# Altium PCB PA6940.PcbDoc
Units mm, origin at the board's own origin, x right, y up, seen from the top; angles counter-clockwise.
Board outline 34.99 x 16 mm, 2 copper layers (Top Layer, Bottom Layer), stack 1.57 mm thick; 7 components, 10 nets, 38 pads, 75 vias.
Unrouted connection lines stored in the file: 10.
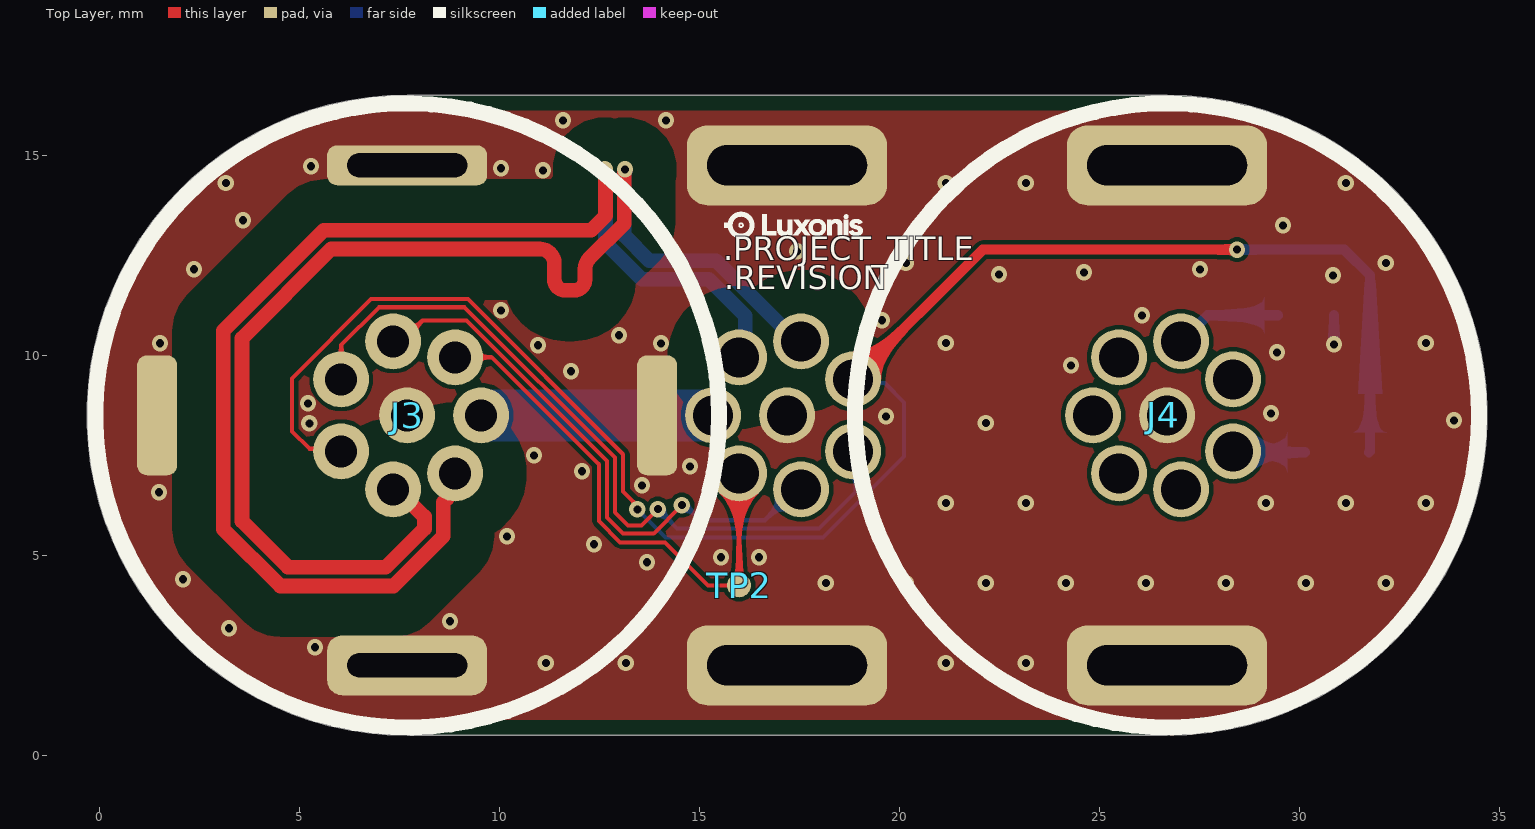
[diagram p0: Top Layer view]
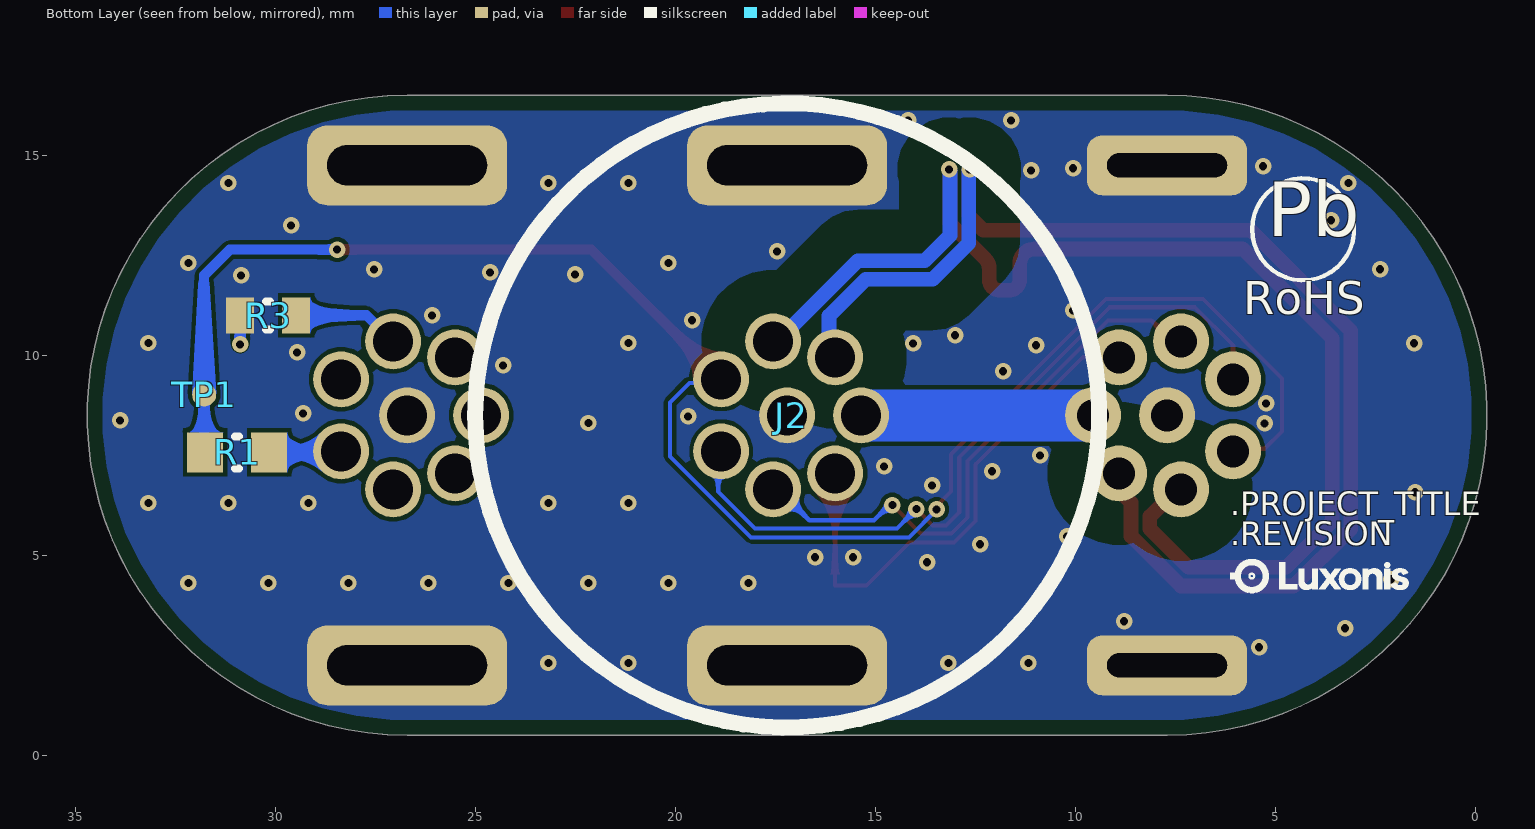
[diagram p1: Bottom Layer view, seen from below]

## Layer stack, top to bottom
Top Solder: solder mask 0.0254, SM-001, Dk 4
Top Layer: signal copper 0.035
Dielectric 1: core 1.5, Core-043, Dk 4.3
Bottom Layer: signal copper 0.035
Bottom Solder: solder mask 0.0254, SM-001, Dk 4

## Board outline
7.703,0.5 cw(c7.703,8.5) 7.703,16.5 26.7,16.5 cw(c26.7,8.5) 26.7,0.5

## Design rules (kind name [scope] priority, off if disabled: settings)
AssemblyTestPointUsage [All] p1: valid=2
AssemblyTestpoint [(IsPad And (OnTopLayer Or OnBottomLayer)) Or (IsVia) Or (IsPad And OnMultiLayer)] p1: testpointundercomponent=FALSE minsize=0.381 maxsize=2.54 preferedsize=1.524 minholesize=0 maxholesize=2.54 preferedholesize=0.813 testpointgrid=0.025 usegrid=FALSE gridtolerance=0 allowsidebottom=TRUE
BoardOutlineClearance [not InPolygonClass('ToEdge')] p1: gap=0.381 ignorepadtopadclearanceinfootprint=FALSE
Clearance DIFF_PAIR_GND [InPolygon vs InAnyDifferentialPair] p1: gap=1.08 ignorepadtopadclearanceinfootprint=FALSE
Clearance [All] p2: gap=0.1 ignorepadtopadclearanceinfootprint=FALSE
ComponentClearance [HasFootprint('FIDUCIAL_ROUND_1MM') or HasFootprint('TP100_200_NS') vs HasFootprint('FIDUCIAL_ROUND_1MM') or HasFootprint('TP100_200_NS')] p1: gap=-0.003 collisioncheckmode=3 verticalgap=2540 showdistances=FALSE
DiffPairsRouting 90ohm [InDifferentialPair('USB_D')] p1: maxlimit=0.1 minlimit=0.1 mostfreqgap=0.1 toplayer_minwidth=0.366 toplayer_maxwidth=0.366 toplayer_prefwidth=0.366 bottomlayer_minwidth=0.366 bottomlayer_maxwidth=0.366 bottomlayer_prefwidth=0.366 impedanceprofiledriven=TRUE impedanceprofileid={4F08DFFA-C90D-4D92-B63A-58C89057396F} impedanceprofilevalue=90.000000 maxuncoupledlength=12.7
DiffPairsRouting 100ohm [InDifferentialPairClass('100ohm')] p2: maxlimit=0.11 minlimit=0.11 mostfreqgap=0.11 toplayer_minwidth=0.173 toplayer_maxwidth=0.173 toplayer_prefwidth=0.173 bottomlayer_minwidth=0.173 bottomlayer_maxwidth=0.173 bottomlayer_prefwidth=0.173 maxuncoupledlength=12.7
FabricationTestPointUsage [All] p1: valid=2 allowmultiple=TRUE
FabricationTestpoint [(IsPad And (OnTopLayer Or OnBottomLayer)) Or (IsVia) Or (IsPad And OnMultiLayer)] p1: side=3 testpointundercomponent=TRUE minsize=0.508 maxsize=2.54 preferedsize=1.524 minholesize=0 maxholesize=1.016 preferedholesize=0.813 testpointgrid=0.025 allowsidetop=TRUE allowsidebottom=TRUE usegrid=FALSE gridtolerance=0
HoleSize [All] p1: absolutevalues=TRUE maxlimit=25.4 minlimit=0.2 maxpercent=80.000 minpercent=20.000
HoleToHoleClearance [All] p1: gap=0.254 allowstackedmicrovias=FALSE
MatchedLengths "Schematic Matched Net Lengths" [InNetClass('USB')] p1: tolerance=25.4 checknetsindiffpair=FALSE checkdiffpairvsdiffpair=TRUE checkxsignals=TRUE checkothers=TRUE usedelayunits=TRUE delaytolerance=1.000000
MatchedLengths DIFF-pairs [InDifferentialPairClass('All Differential Pairs')] p2: tolerance=0.635 checknetsindiffpair=TRUE checkdiffpairvsdiffpair=FALSE checkxsignals=FALSE checkothers=FALSE
MatchedLengths MIPI [InNetClass('SENSORMIPI')] p3: tolerance=25.4 checknetsindiffpair=FALSE checkdiffpairvsdiffpair=TRUE checkxsignals=TRUE checkothers=TRUE usedelayunits=TRUE delaytolerance=1.000000
MinimumSolderMaskSliver [not (HasFootprint('DF40HC-3.0-100DS-0.4V_minpad') or HasFootprint('TPD4E02B04DQAR') or HasFootprint('105450-0101'))] p1: minsoldermaskwidth=0.076
PolygonConnect [All] p1: thpad.connectstyle=Direct thpad.reliefconductorwidth=0.254 thpad.reliefentries=4 thpad.polygonreliefangle="90 Angle" thpad.airgapwidth=0.254 smdpad.connectstyle=Relief smdpad.reliefconductorwidth=0.254 smdpad.reliefentries=4 smdpad.polygonreliefangle="90 Angle" smdpad.airgapwidth=0.254 via.connectstyle=Direct via.reliefconductorwidth=0.254 via.reliefentries=4 via.polygonreliefangle="90 Angle" via.airgapwidth=0.254
RoutingVias RoutingVias_Diff [InDifferentialPairClass('All Differential Pairs')] p1: holewidth=0.254 width=0.508 viastyle="Through Hole" minholewidth=0.2 minwidth=0.4 maxholewidth=25.4 maxwidth=25.4 useviatemplates=TRUE viatemplateguid#1={ACCFCD4B-B46F-49C8-88C0-BB7C3FDCF5E3} viatemplatename#1=v41h20m0mx0
RoutingVias [All] p2: holewidth=0.254 width=0.508 viastyle="Through Hole" minholewidth=0.2 minwidth=0.4 maxholewidth=25.4 maxwidth=25.4 useviatemplates=TRUE viatemplateguid#1={ACCFCD4B-B46F-49C8-88C0-BB7C3FDCF5E3} viatemplatename#1=v41h20m0mx0
SilkToSilkClearance [All] p1: silktosilkclearance=0.025
SilkToSolderMaskClearance [InPadClass('All Pads')] p1: minsilkscreentomaskgap=0 clearancetoexposedcopper=FALSE
SolderMaskExpansion [All] p1: expansion=0.102 istentingtop=FALSE
UnRoutedNet [All] p1: checkbadconnections=TRUE
Width [All] p1: maxlimit=10 minlimit=0.102 preferedwidth=0.254 minimp=50.000000 maximp=50.000000 favimp=50.000000
18 further rules are at their usual default settings.

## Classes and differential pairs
net class USB: USB_D_N USB_D_P
differential pair USB_D: +USB_D_P -USB_D_N

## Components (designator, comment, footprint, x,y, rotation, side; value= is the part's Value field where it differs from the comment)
J2 "1424236" 1424236 17.2,8.5 r270 bottom locked
J3 "08-3203-08-xxx" 08-3203-08-XXX 7.703,8.5 r270 top locked
J4 "1424236" 1424236 26.7,8.5 r90 top locked
R1 "CRCW060310R0FKEA" RESC0603(1608)_N 30.95,7.575 r180 bottom value=10
R3 "RC0603FR-07220RL" RESC0603(1608)_L 30.175,11 r180 bottom value=220
TP1 "TPAD6R" TP06R 31.775,9.017 r270 bottom
TP2 "TPAD6R" TP06R 16,4.25 r270 top

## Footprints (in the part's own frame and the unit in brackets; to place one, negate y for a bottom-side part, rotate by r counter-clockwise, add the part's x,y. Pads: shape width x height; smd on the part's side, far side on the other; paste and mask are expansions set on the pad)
08-3203-08-XXX [mm]
  round 1.4 hole 0.8 paste-10 mask+0.05: 1(-0.9,-1.65) 2(0.9,-1.65) 3(1.85,-0.35) 4(1.45,1.2) 5(0,1.85) 6(-1.45,1.2) 7(-1.85,-0.35) 8(0,0)
  rrect50% 3x1 smd paste-10 mask+0.05: 9(0,6.25) 11(0,-6.25)
  rrect50% 1.5x4 hole 0.6 slot 3 at 90 deg paste-10 mask+0.05: 10(6.25,0)
  rrect50% 1x4 / inner rrect50% 1.5x4 / far side rrect50% 1.5x4 hole 0.6 slot 3 at 90 deg paste-10 mask+0.05: 12(-6.25,0)
  silkscreen extent -7.8,-7.8 7.8,7.8, body extent -6.4,-6.4 6.4,6.4, height 15.53
1424236 [mm]
  round 1.4 hole 1 paste-10 mask+0.05: 1(-0.9,-1.65) 2(0.9,-1.65) 3(1.85,-0.35) 4(1.45,1.2) 5(0,1.85) 6(-1.45,1.2) 7(-1.85,-0.35) 8(0,0)
  rrect50% 2x5 hole 1 slot 4 at 90 deg paste-10 mask+0.05: 9(6.25,0) 10(-6.25,0)
  silkscreen extent -7.8,-7.8 7.8,7.8, body extent -6.4,-6.4 6.4,6.4, height 17.2
RESC0603(1608)_L [mm] "Chip Resistor, Body 1.6x0.8mm, IPC High Density"
  rect 0.7x0.9 smd: 1(-0.7,0) 2(0.7,0)
  silkscreen extent -0.05,-0.35 0.05,0.35, body extent -0.85,-0.47 0.85,0.47, height 0.6
RESC0603(1608)_N [mm] "Chip Resistor, Body 1.6x0.8mm, IPC Medium Density"
  rect 0.9x1 smd: 1(-0.8,0) 2(0.8,0)
  silkscreen extent -0.05,-0.4 0.05,0.4, body extent -0.85,-0.47 0.85,0.47, height 0.6
TP06R [mm] "Testpoint, round, d=0.6mm"
  round 0.6 smd paste-1: 1(0,0)

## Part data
J2 J4: library part CMP-002-00173-2, "Circular Connector", Manufacturer 1="Phoenix Contact"
J3: library part CMP-002-00116-2, "M8 Circular Connector", Manufacturer 1=KingTop, Manufacturer Part Number 1=08-3203-08-XXX
R1: library part CMP-115-000012-5, "RES SMD 10 OHM 1% 1/10W 0603", Case/Package=0603, Manufacturer 1=Vishay, Max Operating Temperature=155°C, Min Operating Temperature=-55°C, Power Rating=100mW, Temperature Coefficient=100ppm/°C, Tolerance=1%, Voltage Rating=75V
R3: library part CMP-009-00346-1, "RES SMD 220 OHM 1% 0.1W 0603", Case/Package=0603, Manufacturer 1=Yageo, Power Rating=100mW, Tolerance=1%, Voltage Rating=75V
TP1 TP2: library part CMP-00028-00002-3, "0.6mm round"

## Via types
v1: diameter 0.406, hole 0.203, Top Layer to Bottom Layer, tented both sides, 46 vias
v2: diameter 0.41, hole 0.2, Top Layer to Bottom Layer, tented both sides, 29 vias

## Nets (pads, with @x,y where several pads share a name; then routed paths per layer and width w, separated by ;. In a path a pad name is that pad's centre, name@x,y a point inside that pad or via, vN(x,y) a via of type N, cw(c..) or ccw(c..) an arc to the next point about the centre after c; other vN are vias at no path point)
BOOT/WS_5V: J2.2 J3.1 | length 19
  Top Layer w0.102: J3.1 6.053,10.253 7.001,11.201 9.141,11.201 12.898,7.443 12.898,6.076 13.225,5.75 13.565,5.75 v2(13.97,6.155)
  Bottom Layer w0.102: v2(13.97,6.155) 14.45,5.675 18,5.675 18.925,6.6 18.925,7.525 J2.2
FSYNC/SD0_5V: J2.1 J3.2 R1.1 TP1.1 | length 44.6
  Top Layer w0.102: J3.2 5.989,7.665 5.26,7.665 4.825,8.1 4.825,9.425 6.802,11.402 9.224,11.402 13.1,7.527 13.1,6.6 13.355,6.345 13.355,6.337 13.46,6.232 v2(13.46,6.148)
  Top Layer w0.254: J2.1 22.091,12.641 v2(28.45,12.641)
  Bottom Layer w0.102: v2(13.46,6.148) 14.159,5.45 18.1,5.45 20.125,7.475 20.125,8.825 19.643,9.307 18.943,9.307 J2.1
  Bottom Layer w0.254: v2(28.45,12.641) 31.134,12.641 31.775,12 TP1.1 31.775,7.6 R1.1
GND: J2.8 J2.9 J2.10 J3.8 J3.9 J3.10 J3.11 J3.12 J4.8 J4.9 J4.10 R3.1 | length 0.7
  Bottom Layer w0.254: v2(30.875,10.275) R3.1
  other v1: 11.17,2.31 13.17,2.31 21.17,2.31 23.17,2.31 5.4,2.7 3.25,3.175 8.775,3.35 18.17,4.31 20.17,4.31 22.17,4.31 24.17,4.31 26.17,4.31 28.17,4.31 30.17,4.31 32.17,4.31 2.1,4.4 13.7,4.825 15.55,4.95 16.5,4.95 12.375,5.275 10.2,5.474 21.17,6.31 23.17,6.31 29.17,6.31 31.17,6.31 33.17,6.31 1.5,6.575 12.075,7.1 22.17,8.31 11.8,9.6 10.975,10.25 1.525,10.3 21.17,10.31 33.17,10.31 13,10.5 19.575,10.875 2.375,12.15 20.17,12.31 32.17,12.31 3.6,13.375 3.17,14.31 21.17,14.31 23.17,14.31 31.17,14.31 10.05,14.675 5.3,14.725
  other v2: 13.575,6.75 14.775,7.225 10.875,7.5 5.26,8.3 33.875,8.375 19.675,8.475 29.3,8.55 5.225,8.8 24.3,9.75 29.45,10.075 14.05,10.3 26.075,11 10.05,11.125 30.85,12 22.5,12.025 24.625,12.075 27.525,12.15 17.45,12.6 29.6,13.25 11.1,14.625 11.6,15.875 14.175,15.875
GPIO3: J4.3 R3.2 | length 2.7
  Bottom Layer w0.254: J4.3 27.068,10.35 27.718,11 R3.2
GPIO3_5V: J2.3 J3.7 | length 14.2
  Top Layer w0.102: J3.7 7.573,10.35 8.098,10.875 9.182,10.875 12.697,7.36 12.697,5.95 13.096,5.55 13.139,5.55 13.141,5.548 13.649,5.548 13.651,5.55 13.869,5.55 v2(14.572,6.253)
  Bottom Layer w0.102: v2(14.572,6.253) 14.655,6.253 15.032,5.877 16.646,5.877 17.419,6.65 J2.3
NetJ4_1: J4.1 R1.2 | length 1.8
  Bottom Layer w0.254: J4.1 28.375,7.575 R1.2
STRB/SCK_5V: J2.4 J3.6 TP2.1 | length 13.1
  Top Layer w0.102: J3.6 9.821,9.95 12.495,7.276 12.495,5.855 13.025,5.325 14.147,5.325 15.222,4.25 TP2.1 J2.4
USB_D_N: J2.6 J3.4 | length 32.4
  Top Layer w0.366: J3.4 8.705,6.852 8.705,6.422 8.602,6.319 8.602,5.474 7.363,4.234 4.532,4.234 3.109,5.657 3.109,10.618 5.616,13.125 12.3,13.125 12.662,13.487 12.662,14.628 v2(12.64,14.65)
  Bottom Layer w0.366: v2(12.64,14.65) 12.662,14.628 12.662,12.804 13.566,11.9 15.238,11.9 16.154,10.985 16.154,10.104 J2.6
USB_D_P: J2.7 J3.3 | length 32.1
  Top Layer w0.366: J3.3 7.456,6.65 8.136,5.97 8.136,5.667 7.17,4.7 4.725,4.7 3.575,5.85 3.575,10.425 5.809,12.659 10.068,12.659 11.017,12.659 cw(c11.017,12.293) 11.383,12.293 11.383,11.895 ccw(c11.651,11.895) 11.651,11.626 11.881,11.626 ccw(c11.881,11.895) 12.149,11.895 12.149,12.164 cw(c12.515,12.164) 12.257,12.423 13.125,13.291 13.128,13.294 13.128,14.597 13.15,14.619 v2(13.15,14.65)
  Bottom Layer w0.366: v2(13.15,14.65) 13.15,14.619 13.128,14.597 13.128,12.997 13.759,12.366 15.431,12.366 17.447,10.35 J2.7
VBUS: J2.5 J3.5 | length 5.8
  Bottom Layer w1.3: J3.5 J2.5
pads on no net: J4.2 J4.4 J4.5 J4.6 J4.7

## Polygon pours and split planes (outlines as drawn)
GND on Bottom Layer "GND_L02_P006" (solid, pour order 6): 0,2.5 0,14.5 cw(c2.5,14.5) 2.5,17 38.5,17 cw(c38.5,14.5) 41,14.5 41,2.5 cw(c38.5,2.5) 38.5,0 2.5,0 cw(c2.5,2.5)
GND on Top Layer "GND_L01_P002" (solid, pour order 2): 0,2.5 0,14.5 cw(c2.5,14.5) 2.5,17 38.5,17 cw(c38.5,14.5) 41,14.5 41,2.5 cw(c38.5,2.5) 38.5,0 2.5,0 cw(c2.5,2.5)

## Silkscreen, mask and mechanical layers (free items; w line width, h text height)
Top Overlay:
  drawing of 10 lines, arcs and shapes, not listed
  text ".PROJECT_TITLE" at 15.6,12.175 h1
  text ".REVISION" at 15.625,11.45 h1
Bottom Overlay:
  drawing of 11 lines, arcs and shapes, not listed
  text "Pb" at 5.198,12.522 h2.34
  text "RoHS" at 5.8,10.75 h1.4
  text ".PROJECT_TITLE" at 6.125,5.8 h1
  text ".REVISION" at 6.125,5.05 h1
Board:
  the board outline again, w0.025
